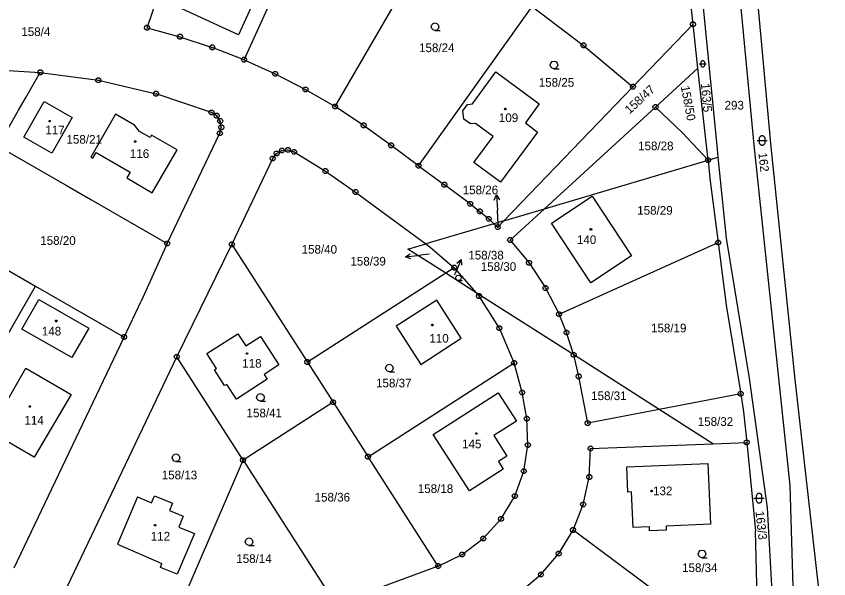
# Model space of a CAD drawing. Extents: x -779723 to -777378, y -1011169 to -1009297.
# Drawn here: x -779371.6 to -779212.2, y -1010124.4 to -1010014.1 of the extents above; entities that cross this region are included whole.
import ezdxf

# ---------------------------------------------------------------- set-up
doc = ezdxf.new("R2010")
doc.units = 0
for name, color, linetype in [('Default', 7, 'Continuous'), ('KN_HRANICE', 7, 'Continuous'), ('KN_KULTURY', 7, 'Continuous'), ('KN_PARCELY', 7, 'Continuous')]:
    doc.layers.add(name, color=color, linetype=linetype)

# ---------------------------------------------------------------- blocks, each defined once
blk = doc.blocks.new('304')
at = {"layer": 'Default'}
blk.add_lwpolyline([(0, 0), (-0.38, 0.1), (-0.65, 0.37), (-0.75, 0.74), (-0.65, 1.11), (-0.38, 1.38), (-0.01, 1.48), (0.36, 1.38), (0.63, 1.11), (0.73, 0.73), (0.63, 0.35), (0.36, 0.08), (-0.02, -0.02), (0.98, -0.02)], dxfattribs=at)
blk = doc.blocks.new('316')
at = {"layer": 'Default'}
for points in [[(-0.5, 1.5), (-0.4, 1.79), (-0.15, 1.97), (0.16, 1.97), (0.41, 1.79), (0.51, 1.5), (0.51, 0.5), (0.41, 0.21), (0.16, 0.03), (-0.15, 0.03), (-0.4, 0.21), (-0.5, 0.5), (-0.5, 1.5)], [(-1, 1), (0.27, 1), (1, 1)]]:
    blk.add_lwpolyline(points, dxfattribs=at)
blk = doc.blocks.new('10292')
at = {"layer": 'Default'}
blk.add_line((0, 3), (0, 0), dxfattribs=at)
blk.add_lwpolyline([(-0.5, 2), (0, 3), (0.5, 2)], dxfattribs=at)
blk = doc.blocks.new('105')
at = {"layer": 'Default'}
blk.add_line((-0.12, 0), (0.12, 0), dxfattribs=at)
blk.add_lwpolyline([(0.15, 0.48), (0.4, 0.3), (0.5, 0.01), (0.4, -0.28), (0.15, -0.46), (-0.16, -0.46), (-0.41, -0.28), (-0.51, 0.01), (-0.41, 0.3), (-0.16, 0.48), (0.15, 0.48)], dxfattribs=at)
blk = doc.blocks.new('402')
at = {"layer": 'Default'}
blk.add_lwpolyline([(0.09, 0.15), (0.18, 0), (0.09, -0.15), (-0.09, -0.15), (-0.18, 0), (-0.09, 0.15), (0.09, 0.15)], dxfattribs=at)

msp = doc.modelspace()

# ---------------------------------------------------------------- linework, layer by layer
at = {"layer": 'KN_HRANICE'}
for p, q in [((-779234.8, -1009917.25), (-779223.59, -1010039.03)), ((-779226.79, -1010039.25), (-779233.71, -1009966.95)), ((-779238.78, -1010015.64), (-779243.85, -1009969.77)), ((-779241.08, -1009968.91), (-779234.07, -1010040.11)), ((-779326.85, -1010022.6), (-779312.49, -1009991.16)), ((-779345.89, -1010016.32), (-779340.12, -1009999.61)), ((-779309, -1010031.79), (-779290.22, -1009999.35)), ((-779292.64, -1010043.39), (-779270.32, -1010012.18)), ((-779270.32, -1010012.18), (-779260.26, -1010019.77)), ((-779238.78, -1010015.64), (-779250.57, -1010027.88)), ((-779237.83, -1010024.25), (-779238.78, -1010015.64)), ((-779345.89, -1010016.32), (-779339.43, -1010018.09)), ((-779339.43, -1010018.09), (-779333.1, -1010020.18)), ((-779326.85, -1010022.6), (-779333.1, -1010020.18)), ((-779260.26, -1010019.77), (-779250.57, -1010027.88)), ((-779326.85, -1010022.6), (-779320.74, -1010025.36)), ((-779378.05, -1010024.4), (-779366.83, -1010025.07)), ((-779369.72, -1010030.1), (-779366.83, -1010025.07)), ((-779366.83, -1010025.07), (-779355.43, -1010026.62)), ((-779320.74, -1010025.36), (-779314.79, -1010028.42)), ((-779282.06, -1010031.21), (-779277.45, -1010024.98)), ((-779277.45, -1010024.98), (-779268.99, -1010031.25)), ((-779246.15, -1010031.88), (-779237.83, -1010024.25)), ((-779235.83, -1010042.28), (-779237.83, -1010024.25)), ((-779355.43, -1010026.62), (-779344.13, -1010029.26)), ((-779314.79, -1010028.42), (-779309, -1010031.79)), ((-779275.87, -1010054.16), (-779250.57, -1010027.88)), ((-779371.1, -1010032.49), (-779369.72, -1010030.1)), ((-779333.23, -1010032.93), (-779344.13, -1010029.26)), ((-779370.06, -1010037.75), (-779366.05, -1010030.8)), ((-779366.05, -1010030.8), (-779360.55, -1010033.95)), ((-779303.4, -1010035.47), (-779309, -1010031.79)), ((-779283.96, -1010032.63), (-779283.04, -1010031.37)), ((-779283.04, -1010031.37), (-779282.06, -1010031.21)), ((-779268.99, -1010031.25), (-779271.67, -1010034.94)), ((-779246.15, -1010031.88), (-779267.94, -1010051.81)), ((-779240.94, -1010036.84), (-779246.15, -1010031.88)), ((-779375.15, -1010039.53), (-779371.1, -1010032.49)), ((-779352.07, -1010033.25), (-779356.91, -1010041.67)), ((-779348.33, -1010035.44), (-779352.07, -1010033.25)), ((-779332.22, -1010033.58), (-779333.23, -1010032.93)), ((-779331.53, -1010034.62), (-779332.22, -1010033.58)), ((-779283.73, -1010034.23), (-779283.96, -1010032.63)), ((-779360.55, -1010033.95), (-779364.55, -1010040.92)), ((-779331.32, -1010035.85), (-779331.53, -1010034.62)), ((-779282.46, -1010035.19), (-779283.73, -1010034.23)), ((-779281.44, -1010035.08), (-779282.46, -1010035.19)), ((-779278, -1010037.62), (-779281.44, -1010035.08)), ((-779271.67, -1010034.94), (-779269.29, -1010036.77)), ((-779347.35, -1010036.64), (-779348.33, -1010035.44)), ((-779345.3, -1010037.84), (-779347.35, -1010036.64)), ((-779331.61, -1010037.02), (-779331.32, -1010035.85)), ((-779298.01, -1010039.38), (-779303.4, -1010035.47)), ((-779269.29, -1010036.77), (-779276.53, -1010046.6)), ((-779235.83, -1010042.28), (-779240.94, -1010036.84)), ((-779364.55, -1010040.92), (-779370.06, -1010037.75)), ((-779345.02, -1010037.36), (-779345.3, -1010037.84)), ((-779340.01, -1010040.29), (-779345.02, -1010037.36)), ((-779341.93, -1010058.63), (-779331.61, -1010037.02)), ((-779281.78, -1010042.74), (-779278, -1010037.62)), ((-779375.15, -1010039.53), (-779361.56, -1010047.34)), ((-779292.64, -1010043.39), (-779298.01, -1010039.38)), ((-779219.75, -1010106.05), (-779226.79, -1010039.25)), ((-779223.59, -1010039.03), (-779218.82, -1010085.26)), ((-779356.91, -1010041.67), (-779356.52, -1010041.89)), ((-779356.52, -1010041.89), (-779355.87, -1010040.77)), ((-779355.87, -1010040.77), (-779349.23, -1010044.65)), ((-779344.91, -1010048.67), (-779340.01, -1010040.29)), ((-779321.24, -1010041.97), (-779320.47, -1010040.98)), ((-779320.47, -1010040.98), (-779319.43, -1010040.4)), ((-779319.43, -1010040.4), (-779318.23, -1010040.28)), ((-779318.23, -1010040.28), (-779317.04, -1010040.66)), ((-779317.04, -1010040.66), (-779310.89, -1010044.42)), ((-779234.07, -1010040.11), (-779233.9, -1010041.71)), ((-779329.26, -1010058.8), (-779321.24, -1010041.97)), ((-779276.53, -1010046.6), (-779281.78, -1010042.74)), ((-779267.94, -1010051.81), (-779235.83, -1010042.28)), ((-779235.83, -1010042.28), (-779233.9, -1010041.71)), ((-779235.83, -1010042.28), (-779235.48, -1010045.87)), ((-779233.9, -1010041.71), (-779232.26, -1010057.56)), ((-779349.23, -1010044.65), (-779349.88, -1010045.77)), ((-779310.89, -1010044.42), (-779304.98, -1010048.53)), ((-779292.64, -1010043.39), (-779287.56, -1010047.11)), ((-779349.88, -1010045.77), (-779344.91, -1010048.67)), ((-779235.48, -1010045.87), (-779233.85, -1010058.45)), ((-779361.56, -1010047.34), (-779356.91, -1010050.02)), ((-779282.51, -1010050.85), (-779287.56, -1010047.11)), ((-779304.98, -1010048.53), (-779291.21, -1010058.71)), ((-779266.57, -1010054.66), (-779258.57, -1010049.37)), ((-779258.57, -1010049.37), (-779250.85, -1010061.04)), ((-779356.91, -1010050.02), (-779341.93, -1010058.63)), ((-779282.51, -1010050.85), (-779280.61, -1010052.33)), ((-779280.61, -1010052.33), (-779278.85, -1010053.8)), ((-779275.87, -1010054.16), (-779267.94, -1010051.81)), ((-779274.64, -1010057.94), (-779267.94, -1010051.81)), ((-779278.85, -1010053.8), (-779277.83, -1010054.74)), ((-779275.87, -1010054.16), (-779277.83, -1010054.74)), ((-779277.09, -1010055.43), (-779275.87, -1010054.16)), ((-779277.83, -1010054.74), (-779291.21, -1010058.71)), ((-779277.83, -1010054.74), (-779277.09, -1010055.43)), ((-779258.86, -1010066.35), (-779266.57, -1010054.66)), ((-779385.17, -1010056.96), (-779367.78, -1010066.96)), ((-779232.26, -1010057.56), (-779227.75, -1010085.02)), ((-779341.93, -1010058.63), (-779347.05, -1010069.95)), ((-779340.06, -1010080.85), (-779329.26, -1010058.8)), ((-779329.26, -1010058.8), (-779314.44, -1010081.88)), ((-779294.7, -1010059.75), (-779291.21, -1010058.71)), ((-779291.21, -1010058.71), (-779290.44, -1010059.28)), ((-779274.64, -1010057.94), (-779270.95, -1010062.42)), ((-779265.07, -1010072.49), (-779233.85, -1010058.45)), ((-779233.85, -1010058.45), (-779232.26, -1010070.73)), ((-779287.31, -1010064.46), (-779294.7, -1010059.75)), ((-779290.44, -1010059.28), (-779285.62, -1010063.38)), ((-779250.85, -1010061.04), (-779258.86, -1010066.35)), ((-779285.62, -1010063.38), (-779287.31, -1010064.46)), ((-779285.62, -1010063.38), (-779281.34, -1010068.27)), ((-779270.95, -1010062.42), (-779267.73, -1010067.35)), ((-779287.31, -1010064.46), (-779314.44, -1010081.88)), ((-779281.34, -1010068.27), (-779287.31, -1010064.46)), ((-779392.71, -1010110.31), (-779367.78, -1010066.96)), ((-779367.78, -1010066.96), (-779350.39, -1010076.96)), ((-779280.77, -1010068.92), (-779281.34, -1010068.27)), ((-779262.19, -1010080.48), (-779281.34, -1010068.27)), ((-779267.73, -1010067.35), (-779265.07, -1010072.49)), ((-779370.44, -1010075.43), (-779367.14, -1010069.6)), ((-779367.14, -1010069.6), (-779357.34, -1010075.2)), ((-779350.39, -1010076.96), (-779347.05, -1010069.95)), ((-779289.06, -1010069.75), (-779296.99, -1010074.85)), ((-779284.27, -1010077.21), (-779289.06, -1010069.75)), ((-779276.77, -1010075.24), (-779280.77, -1010068.92)), ((-779232.26, -1010070.73), (-779229.43, -1010088.1)), ((-779263.6, -1010076.09), (-779265.07, -1010072.49)), ((-779296.99, -1010074.85), (-779292.21, -1010082.32)), ((-779360.65, -1010080.96), (-779370.44, -1010075.43)), ((-779357.34, -1010075.2), (-779360.65, -1010080.96)), ((-779334.15, -1010080.2), (-779328.11, -1010076.32)), ((-779328.11, -1010076.32), (-779326.54, -1010078.72)), ((-779273.87, -1010082.04), (-779276.77, -1010075.24)), ((-779262.23, -1010080.33), (-779263.6, -1010076.09)), ((-779371.98, -1010122.22), (-779350.39, -1010076.96)), ((-779326.54, -1010078.72), (-779323.64, -1010076.83)), ((-779323.64, -1010076.83), (-779320.02, -1010082.41)), ((-779292.21, -1010082.32), (-779284.27, -1010077.21)), ((-779362.17, -1010127.2), (-779340.06, -1010080.85)), ((-779327.06, -1010101.1), (-779340.06, -1010080.85)), ((-779332.28, -1010083.11), (-779334.15, -1010080.2)), ((-779262.19, -1010080.48), (-779262.23, -1010080.33)), ((-779245.44, -1010091.17), (-779262.19, -1010080.48)), ((-779261.21, -1010084.68), (-779262.19, -1010080.48)), ((-779376.78, -1010095.43), (-779369.65, -1010083.1)), ((-779369.65, -1010083.1), (-779360.78, -1010088.23)), ((-779332.67, -1010083.38), (-779332.28, -1010083.11)), ((-779320.02, -1010082.41), (-779322.93, -1010084.3)), ((-779314.44, -1010081.88), (-779309.39, -1010089.76)), ((-779302.53, -1010100.44), (-779273.87, -1010082.04)), ((-779272.31, -1010087.85), (-779273.87, -1010082.04)), ((-779330.69, -1010086.49), (-779332.67, -1010083.38)), ((-779322.93, -1010084.3), (-779322.31, -1010085.25)), ((-779259.45, -1010093.86), (-779261.21, -1010084.68)), ((-779330.27, -1010086.25), (-779330.69, -1010086.49)), ((-779328.37, -1010089.12), (-779330.27, -1010086.25)), ((-779322.31, -1010085.25), (-779328.37, -1010089.12)), ((-779227.75, -1010085.02), (-779224.22, -1010110.43)), ((-779218.82, -1010085.26), (-779212.16, -1010143.8)), ((-779271.38, -1010092.97), (-779272.31, -1010087.85)), ((-779360.78, -1010088.23), (-779368.02, -1010100.51)), ((-779229.43, -1010088.1), (-779245.44, -1010091.17)), ((-779229.43, -1010088.1), (-779228.86, -1010091.61)), ((-779309.39, -1010089.76), (-779327.06, -1010101.1)), ((-779309.39, -1010089.76), (-779302.53, -1010100.44)), ((-779245.44, -1010091.17), (-779259.45, -1010093.86)), ((-779234.88, -1010097.91), (-779245.44, -1010091.17)), ((-779228.86, -1010091.61), (-779228.25, -1010097.65)), ((-779271.18, -1010098.16), (-779271.38, -1010092.97)), ((-779368.02, -1010100.51), (-779376.78, -1010095.43)), ((-779271.98, -1010103.28), (-779271.18, -1010098.16)), ((-779259.13, -1010104.42), (-779258.88, -1010098.83)), ((-779258.88, -1010098.83), (-779234.88, -1010097.91)), ((-779234.88, -1010097.91), (-779228.25, -1010097.65)), ((-779228.25, -1010097.65), (-779226.51, -1010114.99)), ((-779288.77, -1010121.88), (-779302.53, -1010100.44)), ((-779342.01, -1010135.87), (-779327.06, -1010101.1)), ((-779327.06, -1010101.1), (-779310.76, -1010126.49)), ((-779273.75, -1010108.17), (-779271.98, -1010103.28)), ((-779260.32, -1010109.8), (-779259.13, -1010104.42)), ((-779218.61, -1010144.17), (-779219.75, -1010106.05)), ((-779347.76, -1010108.31), (-779345.01, -1010109.46)), ((-779345.01, -1010109.46), (-779344.43, -1010108.09)), ((-779344.43, -1010108.09), (-779340.92, -1010109.57)), ((-779276.44, -1010112.63), (-779273.75, -1010108.17)), ((-779340.92, -1010109.57), (-779341.5, -1010110.95)), ((-779262.32, -1010114.82), (-779260.32, -1010109.8)), ((-779341.5, -1010110.95), (-779338.78, -1010112.1)), ((-779224.22, -1010110.43), (-779222.02, -1010149.91)), ((-779338.78, -1010112.1), (-779339.67, -1010114.22)), ((-779279.93, -1010116.49), (-779276.44, -1010112.63)), ((-779339.67, -1010114.22), (-779336.61, -1010115.51)), ((-779265.13, -1010119.44), (-779262.32, -1010114.82)), ((-779225.9, -1010141.96), (-779262.32, -1010114.82)), ((-779225.9, -1010141.96), (-779226.51, -1010114.99)), ((-779336.61, -1010115.51), (-779339.97, -1010123.49)), ((-779284.08, -1010119.61), (-779279.93, -1010116.49)), ((-779288.77, -1010121.88), (-779284.08, -1010119.61)), ((-779268.62, -1010123.54), (-779265.13, -1010119.44)), ((-779343.25, -1010122.14), (-779342.99, -1010121.4)), ((-779339.97, -1010123.49), (-779343.25, -1010122.14)), ((-779288.77, -1010121.88), (-779301.33, -1010126.54)), ((-779272.77, -1010127.01), (-779268.62, -1010123.54))]:
    msp.add_line(p, q, dxfattribs=at)
for points in [[(-779336.09, -1010005.63), (-779324.79, -1010010.8), (-779327.97, -1010017.71), (-779339.22, -1010012.55)], [(-779289.75, -1010096.1), (-779276.98, -1010087.91), (-779273.41, -1010093.44), (-779277.86, -1010096.28), (-779275.33, -1010100.31), (-779276.97, -1010101.4), (-779276.04, -1010102.9), (-779282.66, -1010107.15)], [(-779235.38, -1010113.69), (-779244.08, -1010114.07), (-779244.05, -1010114.82), (-779247.31, -1010114.94), (-779247.33, -1010114.19), (-779250.56, -1010114.32), (-779250.87, -1010107.34), (-779251.58, -1010107.36), (-779251.76, -1010102.41), (-779235.86, -1010101.78)]]:
    msp.add_lwpolyline(points, close=True, dxfattribs=at)
msp.add_lwpolyline([(-779347.76, -1010108.31), (-779351.7, -1010117.58), (-779342.99, -1010121.4)], dxfattribs=at)
at = {"layer": 'KN_PARCELY'}
for p, q in [((-779276.99, -1010054.84), (-779277.15, -1010052.08)), ((-779290.6, -1010060.73), (-779292.23, -1010060.91)), ((-779285.55, -1010064.78), (-779285.44, -1010064.52))]:
    msp.add_line(p, q, dxfattribs=at)

# ---------------------------------------------------------------- block references
at = {"layer": 'KN_KULTURY'}
for name, p in [('304', (-779289.39, -1010016.86)), ('304', (-779266.04, -1010024.35)), ('402', (-779275.61, -1010032.25)), ('402', (-779364.99, -1010034.65)), ('402', (-779348.21, -1010038.63)), ('316', (-779225.22, -1010039.43)), ('402', (-779258.82, -1010055.84)), ('402', (-779363.71, -1010073.83)), ('402', (-779289.94, -1010074.61)), ('402', (-779326.27, -1010080.19)), ('304', (-779298.35, -1010083.78)), ('304', (-779323.64, -1010089.54)), ('402', (-779368.88, -1010090.59)), ('402', (-779281.29, -1010095.89)), ('304', (-779340.21, -1010101.38)), ('402', (-779246.89, -1010107.14)), ('316', (-779225.83, -1010109.58)), ('402', (-779344.31, -1010113.85)), ('304', (-779325.89, -1010117.84)), ('304', (-779237.02, -1010120.23))]:
    msp.add_blockref(name, p, dxfattribs=at)
for name, p, xscale, yscale in [('316', (-779236.88, -1010024.09), 0.67, 0.67), ('304', (-779284.79, -1010065.87), 0.72, 0.72)]:
    msp.add_blockref(name, p, dxfattribs=dict(at, xscale=xscale, yscale=yscale))
at = {"layer": 'KN_PARCELY'}
for p in [(-779345.89, -1010016.32), (-779238.78, -1010015.64), (-779339.43, -1010018.09), (-779260.26, -1010019.77), (-779333.1, -1010020.18), (-779326.85, -1010022.6), (-779366.83, -1010025.07), (-779320.74, -1010025.36), (-779355.43, -1010026.62), (-779344.13, -1010029.26), (-779314.79, -1010028.42), (-779250.57, -1010027.88), (-779309, -1010031.79), (-779246.15, -1010031.88), (-779333.23, -1010032.93), (-779332.22, -1010033.58), (-779331.53, -1010034.62), (-779303.4, -1010035.47), (-779331.61, -1010037.02), (-779331.32, -1010035.85), (-779319.43, -1010040.4), (-779318.23, -1010040.28), (-779298.01, -1010039.38), (-779321.24, -1010041.97), (-779320.47, -1010040.98), (-779317.04, -1010040.66), (-779292.64, -1010043.39), (-779235.83, -1010042.28), (-779310.89, -1010044.42), (-779304.98, -1010048.53), (-779287.56, -1010047.11), (-779282.51, -1010050.85), (-779280.61, -1010052.33), (-779278.85, -1010053.8), (-779277.09, -1010055.43), (-779274.64, -1010057.94), (-779341.93, -1010058.63), (-779329.26, -1010058.8), (-779233.85, -1010058.45), (-779270.95, -1010062.42), (-779285.62, -1010063.38), (-779267.73, -1010067.35), (-779280.77, -1010068.92), (-779265.07, -1010072.49), (-779276.77, -1010075.24), (-779350.39, -1010076.96), (-779263.6, -1010076.09), (-779340.06, -1010080.85), (-779314.44, -1010081.88), (-779262.19, -1010080.48), (-779273.87, -1010082.04), (-779261.21, -1010084.68), (-779272.31, -1010087.85), (-779229.43, -1010088.1), (-779309.39, -1010089.76), (-779271.38, -1010092.97), (-779259.45, -1010093.86), (-779228.25, -1010097.65), (-779271.18, -1010098.16), (-779258.88, -1010098.83), (-779327.06, -1010101.1), (-779302.53, -1010100.44), (-779271.98, -1010103.28), (-779259.13, -1010104.42), (-779273.75, -1010108.17), (-779260.32, -1010109.8), (-779276.44, -1010112.63), (-779262.32, -1010114.82), (-779279.93, -1010116.49), (-779284.08, -1010119.61), (-779265.13, -1010119.44), (-779288.77, -1010121.88), (-779268.62, -1010123.54)]:
    msp.add_blockref('105', p, dxfattribs=at)
for p, rotation in [((-779277.15, -1010052.08), 3.3804510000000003), ((-779292.23, -1010060.91), 96.42879699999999), ((-779285.44, -1010064.52), -23.158112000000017)]:
    msp.add_blockref('10292', p, dxfattribs=dict(at, rotation=rotation))

# ---------------------------------------------------------------- texts
for s, height, p in [('158/4', 1.7, (-779370.56, -1010017.95)), ('158/24', 1.7, (-779292.53, -1010021.1)), ('158/25', 1.7, (-779269.05, -1010027.89)), ('293', 1.7, (-779232.6, -1010032.36)), ('109', 1.7, (-779276.87, -1010034.82)), ('117', 1.7, (-779365.85, -1010037.23)), ('158/21', 1.7, (-779361.7, -1010039.05)), ('158/28', 1.7, (-779249.56, -1010040.34)), ('116', 1.7, (-779349.26, -1010041.85)), ('158/26', 1.7, (-779283.97, -1010048.97)), ('158/29', 1.7, (-779249.73, -1010052.98)), ('158/26', 0.1, (-779276.97, -1010054.84)), ('158/20', 1.7, (-779366.84, -1010058.89)), ('140', 1.7, (-779261.56, -1010058.73)), ('158/40', 1.7, (-779315.57, -1010060.61)), ('158/39', 0.1, (-779290.58, -1010060.73)), ('158/38', 1.7, (-779282.87, -1010061.76)), ('158/39', 1.7, (-779306, -1010062.95)), ('158/30', 1.7, (-779280.43, -1010064)), ('158/38', 0.1, (-779285.53, -1010064.78)), ('148', 1.7, (-779366.53, -1010076.66)), ('158/19', 1.7, (-779247.03, -1010076.05)), ('110', 1.7, (-779290.51, -1010078.07)), ('118', 1.7, (-779327.22, -1010082.98)), ('158/37', 1.7, (-779300.96, -1010086.83)), ('158/31', 1.7, (-779258.77, -1010089.33)), ('158/41', 1.7, (-779326.37, -1010092.7)), ('114', 1.7, (-779369.94, -1010094.12)), ('158/32', 1.7, (-779237.86, -1010094.39)), ('145', 1.7, (-779284.09, -1010098.77)), ('158/13', 1.7, (-779343.01, -1010104.87)), ('158/18', 1.7, (-779292.78, -1010107.55)), ('132', 1.7, (-779246.63, -1010107.98)), ('158/36', 1.7, (-779313.02, -1010109.22)), ('112', 1.7, (-779345.16, -1010116.87)), ('158/14', 1.7, (-779328.39, -1010121.27)), ('158/34', 1.7, (-779240.93, -1010123.05))]:
    msp.add_text(s, height=height, dxfattribs=at).set_placement(p)
for s, rotation, p in [('158/47', 42.456, (-779251.23, -1010033.34)), ('158/50', 280.635, (-779241.2, -1010027.84)), ('163/5', 275.077, (-779237.24, -1010027.28)), ('162', 276.338, (-779225.97, -1010040.89)), ('163/3', 276.395, (-779226.55, -1010111.16))]:
    msp.add_text(s, height=1.7, rotation=rotation, dxfattribs=at).set_placement(p)

doc.saveas('drawing.dxf')
